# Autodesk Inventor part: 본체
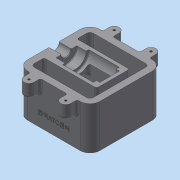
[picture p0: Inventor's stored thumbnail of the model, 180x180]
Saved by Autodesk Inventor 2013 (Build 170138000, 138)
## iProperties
Created: 2018-01
Part Number: 본체
Material: 일반
Document SubType Name: Modeling
Designer: Administrator
Density: 1 g/cm^3
Mass: 368.619 g
Surface Area: 834.392 cm^2
Volume: 368.619 cm^3
Author: Administrator
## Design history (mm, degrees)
sketch "스케치2"
  geometry: L1 (40, 55)-(-40, 55); L2 (-55, 40)-(-55, -40); L3 (-40, -55)-(40, -55); L4 (55, -40)-(55, 40); L5 (55, 55)-(-55, -55); L6 (-55, 55)-(55, -55); A1 r 15 centre (40, -40) between (40, -55) and (55, -40); A2 r 15 centre (40, 40) between (55, 40) and (40, 55); A3 r 15 centre (-40, 40) between (-40, 55) and (-55, 40); A4 r 15 centre (-40, -40) between (-55, -40) and (-40, -55); 1 further point
  constraints: 12 end point, 8 point on circle, 8 point on line, 8 tangent, 4 centre point, 3 equal radius, 2 midpoint, 2 parallel, 1 horizontal, 1 perpendicular
  dimensions: "d0" = 110 distance of L6.end L5.end; "d1" = 110 distance of L5.end L6.start; "d2" = 15 radius of A1
extrude "돌출1" new body sketch "스케치2" distance "d3" = 65; taper "d4" = 0 deg
sketch "스케치3"
  geometry: L1 (-55, 40)-(-55, -40) reference; L2 (-40, -55)-(40, -55) reference; L3 (55, -40)-(55, 40) reference; L4 (40, 55)-(-40, 55) reference; L5 (-35.5, 55)-(-35.5, 65); L6 (-20.5, 55)-(-20.5, 65); L7 (0, 55)-(0, 0); L8 (-35.5, 55)-(-20.5, 55); L9 (35.5, 55)-(20.5, 55); L10 (20.5, 55)-(20.5, 65); L11 (35.5, 55)-(35.5, 65); L12 (-55, 0)-(55, 0); L13 (-20.5, -55)-(-20.5, -65); L14 (-35.5, -55)-(-35.5, -65); L15 (0, -55)-(0, 0); L16 (-35.5, -55)-(-20.5, -55); L17 (40, -55)-(-40, -55); L18 (35.5, -55)-(20.5, -55); L19 (20.5, -55)-(20.5, -65); L20 (35.5, -55)-(35.5, -65); L21 (-40, 55)-(40, 55); A1 r 15 centre (-40, 40) between (-40, 55) and (-55, 40) reference; A2 r 7.5 centre (-28, 65) between (-20.5, 65) and (-35.5, 65); A3 r 7.5 centre (28, 65) between (35.5, 65) and (20.5, 65); A4 r 7.5 centre (-28, -65) between (-35.5, -65) and (-20.5, -65); A5 r 7.5 centre (28, -65) between (20.5, -65) and (35.5, -65); A6 r 15 centre (-40, -40) between (-55, -40) and (-40, -55)
  constraints: 34 end point, 21 symmetric about line, 10 point on circle, 5 centre point, 4 point on line, 3 midpoint, 3 parallel, 2 perpendicular, 2 tangent, 1 collinear, 1 horizontal alignment, 4 other
  dimensions: "d5" = 7.5 radius of A2; "d7" = 28 horizontal distance of L7.end A2.centre; "d8" = 10 distance from line of A2.centre L4
extrude "돌출2" join sketch "스케치3" distance "d9" = 20; taper "d10" = 0 deg
sketch "스케치4"
  geometry: L1 (-55, 40)-(-55, -40) reference; L2 (-40, -55)-(40, -55) reference; L3 (55, -40)-(55, 40) reference; L4 (40, 55)-(-40, 55) reference; L5 (-40, 45)-(40, 45); L6 (45, 40)-(45, -40); L7 (40, -45)-(-40, -45); L8 (-45, -40)-(-45, 40); L9 (-45, 45)-(45, -45); L10 (45, 45)-(-45, -45); A1 r 5 centre (-40, 40) between (-40, 45) and (-45, 40); A2 r 5 centre (40, 40) between (45, 40) and (40, 45); A3 r 5 centre (40, 40) between (45, 40) and (40, 45); A4 r 5 centre (40, -40) between (40, -45) and (45, -40); A5 r 5 centre (-40, -40) between (-45, -40) and (-40, -45); 1 further point
  constraints: 12 end point, 10 point on circle, 10 point on line, 10 tangent, 5 centre point, 2 midpoint, 2 parallel, 1 concentric, 1 horizontal, 1 perpendicular
  dimensions: "d13" = 5 radius of A1; "d14" = 5 radius of A2; "d15" = 5 radius of A4; "d16" = 5 radius of A5; "d17" = 10 distance between parallel lines of L4 L5; "d18" = 10 distance between parallel lines of L3 L6; "d19" = 10 distance between parallel lines of L2 L7 (derived); "d20" = 10 distance between parallel lines of L1 L8 (derived)
extrude "돌출3" cut sketch "스케치4" stored distance "d21" = 20; taper "d22" = 0 deg
sketch "스케치5"
  geometry: L1 (35, 0)-(35, -35); L2 (35, -35)-(-45, -56.436); L3 (55, 0)-(55, -65) reference; L4 (-40, 0)-(40, 0) reference; L5 (-45, 0)-(-40, 0) reference; L6 (35, 0)-(-45, 0); L7 (-45, 0)-(-45, -56.436); L8 (40, -65)-(-40, -65) reference; 1 further point
  constraints: 8 end point, 1 perpendicular, 1 point on line, 1 vertical
  dimensions: "d25" = 20 distance between parallel lines of L3 L1; "d26" = 105 deg angle of L7 L2; "d27" = 30 distance from line of L8 L1.end
extrude "돌출4" join sketch "스케치5" stored distance "d28" = 50; taper "d29" = 0 deg
sketch "스케치7"
  geometry: L1 (-45, 0)-(35, 0) reference; L2 (-55, 0)-(-55, -65) reference; L3 (-55, 0)-(30, 0); L4 (30, 0)-(30, -15); L5 (30, -15)-(25, -15); L6 (25, -15)-(25, -20); L7 (25, -20)-(-22, -20); L8 (-22, -20)-(-22, -16); L9 (-22, -16)-(-36, -16); L10 (-36, -16)-(-36, -7.5); L11 (-36, -7.5)-(-55, -7.5); L12 (-55, 0)-(-55, -7.5); 1 further point
  constraints: 20 end point, 5 perpendicular, 3 parallel, 2 point on line, 1 collinear
  dimensions: "d32" = 15 diameter of L11 L3; "d34" = 32 diameter of L9 L3; "d35" = 40 diameter of L7 L3; "d36" = 30 diameter of L5 L3; "d37" = 5 distance of L4.end L5.end; "d38" = 47 distance of L6.end L7.end; "d39" = 14 distance of L8.end L9.end; "d40" = 19 distance of L10.end L11.end
revolve "회전1" sketch "스케치7" stored, may be unused: angle "d41" = 90 deg
fillet "모깎기1" dims "d42" = 1
sketch "스케치8"
  geometry: L1 (-17, 0)-(-17, -25.757); L2 (-17, -25.757)-(-55, -35.939); L3 (-55, -35.939)-(-55, -53.939); L4 (-55, -53.939)-(20, -33.843); L5 (20, -33.843)-(20, 0); L6 (-55, 0)-(-55, -65) reference; L7 (35, -35)-(-45, -56.436) reference; L8 (-17, 0)-(20, 0); L9 (-22, -16)-(-22, 0) reference; L10 (25, -19)-(25, 0) reference; L11 (-21, 0)-(24, 0) reference; 1 further point
  constraints: 12 end point, 4 parallel, 2 collinear, 1 perpendicular, 1 vertical
  dimensions: "d43" = 5 distance between parallel lines of L7 L4; "d44" = 37 distance of L1.start L5.end; "d45" = 75 deg angle of L6 L2 (derived); "d46" = 18 distance of L2.end L3.end; "d47" = 5 distance between parallel lines of L9 L1; "d48" = 5 distance between parallel lines of L10 L5 (derived)
extrude "돌출5" cut sketch "스케치8" stored distance "d49" = 30; taper "d50" = 0 deg
sketch "스케치9"
  geometry: A1 r 7.5 centre (-28, -65) between (-35.5, -65) and (-20.5, -65) reference; A2 r 7.5 centre (28, -65) between (20.5, -65) and (35.5, -65) reference; A3 r 7.5 centre (28, 65) between (35.5, 65) and (20.5, 65) reference; A4 r 7.5 centre (-28, 65) between (-20.5, 65) and (-35.5, 65) reference; 5 further points
  constraints: 4 coincident
hole "구멍1" sketch "스케치9" at (-28, 65), (28, 65), (28, -65), (-28, -65) diameter "d51" = 3.242; stored, may be unused: countersink angle "d55" = 90 deg, drill point angle "d57" = 118 deg; dims "d52" = 9, "d53" = 4, "d54" = 2, "d56" = 11
fillet "모깎기2" dims "d58" = 3
fillet "모깎기3" dims "d59" = 3
fillet "모깎기4" dims "d60" = 3
fillet "모깎기5" dims "d61" = 3
fillet "모깎기6" dims "d62" = 3
fillet "모깎기7" dims "d63" = 3
fillet "모깎기8" dims "d64" = 3
fillet "모깎기9" dims "d65" = 3
fillet "모깎기10" dims "d66" = 3
chamfer "모따기1" distance "d67" = 1; stored, may be unused: second distance "d68" = 2, angle "d69" = 45 deg
node "작업 평면1"
sketch "스케치10"
  geometry: L1 (-55, 0)-(-55, -65) reference; L2 (40, -65)-(55, -65) reference; 2 further points
  constraints: 1 other
  dimensions: "d73" = 55 horizontal distance of point (0, -45) L1.end; "d74" = 20 vertical distance of L2.end point (0, -45)
feature "엠보싱1" sketch "스케치10" dims "d0" = 110, "d1" = 110, "d2" = 15, "d75" = 0.5, "d76" = 0
node "솔리드1"
